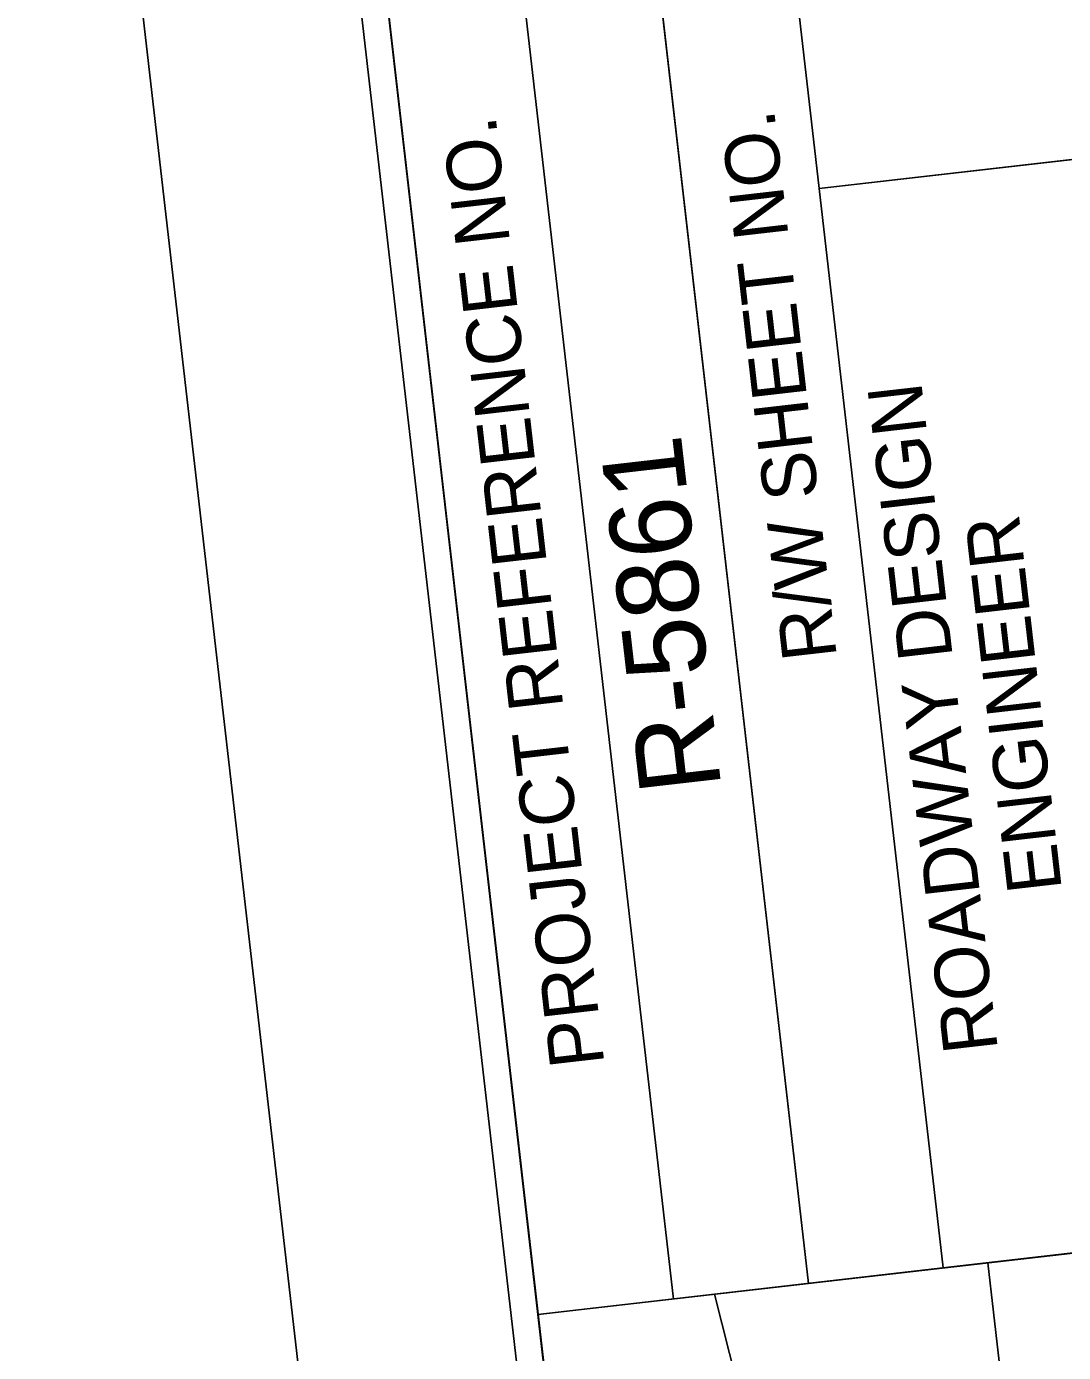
# Model space of a CAD drawing. Extents: x 474105 to 475385, y 502977 to 504774.
# Drawn here: x 474105.4 to 474200.9, y 504432.7 to 504554.8 of the extents above; entities that cross this region are included whole.
import ezdxf

# ---------------------------------------------------------------- set-up
doc = ezdxf.new("R2010")
doc.units = 0
for name, color, linetype in [('Prop Grid Mask', 7, 'Continuous'), ('Sheet Cutting Line CELL', 7, 'Continuous'), ('Sheet Data Field CELL', 7, 'Continuous'), ('Sheet Layout Plan Border', 7, 'Continuous'), ('Sheet Plan CELL', 7, 'Continuous'), ('Sheet Plan Layout CELL', 7, 'Continuous'), ('Sheet Plot Border Inside CELL', 7, 'Continuous'), ('Sheet Plot Border Outside CELL', 7, 'Continuous')]:
    doc.layers.add(name, color=color, linetype=linetype)

msp = doc.modelspace()

# ---------------------------------------------------------------- linework, layer by layer
at = {"layer": 'Prop Grid Mask'}
msp.add_lwpolyline([(474152.5, 504436.15), (474170.46, 504279.81), (474211.89, 504284.57), (474193.93, 504440.91)], close=True, dxfattribs=at)
at = {"layer": 'Sheet Cutting Line CELL'}
msp.add_line((474105.4, 504649.22), (474297.55, 502976.72), dxfattribs=at)
at = {"layer": 'Sheet Layout Plan Border'}
msp.add_lwpolyline([(475344.02, 503264.53), (475192.28, 504585.29), (475112.79, 504576.16), (474903.65, 504485.25), (474306.12, 504619.67), (474302.09, 504654.7), (474324.93, 504455.97), (474152.51, 504436.16), (474168.76, 504438.03), (474279.78, 503999.56), (474242.05, 503987.59), (474254.81, 503913.6), (474216.7, 503877.46), (474300.89, 503144.66)], close=True, dxfattribs=at)
at = {"layer": 'Sheet Plan CELL'}
for p, q in [((474177.42, 504439.01), (474154.57, 504637.74)), ((474177.42, 504439.01), (474154.57, 504637.74)), ((474164.97, 504437.57), (474142.15, 504636.31)), ((474178.41, 504539.84), (474290.13, 504552.68)), ((474177.42, 504439.01), (474189.83, 504440.44))]:
    msp.add_line(p, q, dxfattribs=at)
for points in [[(474129.67, 504634.92), (474300.88, 503144.68), (475344.02, 503264.53), (475172.82, 504754.74)], [(475344.02, 503264.53), (474300.91, 503144.66), (474152.5, 504436.15), (474301.58, 504453.29), (474278.76, 504652.02), (475172.82, 504754.74)], [(474178.41, 504539.84), (474166.98, 504639.17), (474278.76, 504652.02), (474290.19, 504552.68)], [(474152.5, 504436.15), (474129.67, 504634.92), (474154.57, 504637.74), (474177.42, 504439.01)], [(474189.83, 504440.44), (474178.41, 504539.84), (474290.19, 504552.68), (474301.58, 504453.29)]]:
    msp.add_lwpolyline(points, close=True, dxfattribs=at)
at = {"layer": 'Sheet Plan Layout CELL'}
msp.add_lwpolyline([(474367.09, 504421.33), (474339.78, 504659.05), (474129.67, 504634.93), (474156.99, 504397.2)], close=True, dxfattribs=at)
at = {"layer": 'Sheet Plot Border Inside CELL'}
msp.add_lwpolyline([(475364.04, 503112.33), (475173.87, 504767.43), (474125.78, 504647.03), (474315.93, 502991.92)], close=True, dxfattribs=at)
at = {"layer": 'Sheet Plot Border Outside CELL'}
msp.add_lwpolyline([(475385.39, 503101.7), (475193.24, 504774.2), (474105.4, 504649.22), (474297.55, 502976.72)], close=True, dxfattribs=at)

# ---------------------------------------------------------------- texts
at = {"layer": 'Sheet Data Field CELL'}
msp.add_text('R-5861', height=7.5, rotation=96.5538, dxfattribs=at).set_placement((474169.4, 504484.66))
at = {"layer": 'Sheet Plan CELL'}
for s, height, p in [('PROJECT REFERENCE NO.', 5.0001, (474158.63, 504459.2)), ('R/W SHEET NO.', 5.0001, (474180.04, 504496.69)), ('ROADWAY DESIGN', 5.0001, (474194.87, 504460.52)), ('ENGINEER', 5, (474200.76, 504475.28))]:
    msp.add_text(s, height=height, rotation=96.5538, dxfattribs=at).set_placement(p)

doc.saveas('drawing.dxf')
